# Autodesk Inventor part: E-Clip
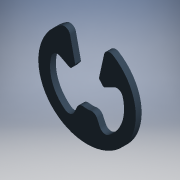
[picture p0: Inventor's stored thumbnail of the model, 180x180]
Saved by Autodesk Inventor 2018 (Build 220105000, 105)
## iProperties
Shininess: 50.0
Compacted: True
Length Units: 11272
Angle Units: 11279
Time Units: 11290
Mass Units: 11286
Length Display Precision: 4
Angle Display Precision: 2
Company: Autodesk
Created: 2000-03
Part Number: E-Clip
Project: Inventor Samples
Document SubType Name: Modeling
Designer: Autodesk, Inc.
Density: 1.13 g/cm^3
Mass: 0.00688314 g
Surface Area: 0.451156 cm^2
Volume: 0.00609128 cm^3
Material: Nylon-6/6
Appearance: Dark Blue Grey
Density: 0.0
Volumn: 0.0
Area: 0.0
PropertySet Name: Model Information
Control State: 0
Master: False
Checked Out: False
Author: Autodesk, Inc.
Revision Number: A
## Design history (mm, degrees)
node "Extrusion1" dims "d2" = 0.381, "d3" = 0
  sketch "Sketch2"
    geometry: C1 r 3.175 at (-5.202, -4.223); C2 r 1.191 at (-5.202, -4.223)
    constraints: 2 centre point, 1 coincident
    dimensions: "d0" = 2.38125 diameter of C2; "d1" = 6.35 diameter of C1
node "Extrusion2" dims "d9" = 0.381, "d10" = 0
  sketch "Sketch3"
    geometry: L1 (-0.635, 0.311)-(0.635, 0.311); L2 (0.635, 0.311)-(1.27, 3.175); L3 (1.27, 3.175)-(-1.27, 3.175); L4 (-1.27, 3.175)-(-0.635, 0.311); C1 r 1.191 at (0, 0) reference; C2 r 3.175 at (0, 0) reference
    constraints: 8 end point, 1 horizontal, 1 parallel, 1 tangent
    dimensions: "d4" = 2.54 distance of L2.end L3.end; "d5" = 1.27 distance of L1.start L1.end; "d6" = 1.27 horizontal distance of C1.centre L3.end (= 0.5 x d4); "d7" = 25 deg angle of L2 L4; "d8" = 0.635 horizontal distance of C1.centre L1.start (= 0.5 x d5)
node "Extrusion3" dims "d16" = 0.381, "d17" = 0
  sketch "Sketch4"
    geometry: L1 (-3.986, -1.29)-(-4.434, -3.313) reference; L2 (-5.97, -3.313)-(-6.418, -1.29) reference; L3 (-5.705, -5.302)-(-6.222, -6.41); L4 (-4.699, -5.302)-(-4.182, -6.41); L5 (-6.281, -4.726)-(-6.281, -4.726); L6 (-5.705, -5.302)-(-5.705, -5.302); L7 (-6.258, -3.673)-(-7.342, -3.109); L8 (-4.146, -3.673)-(-3.062, -3.109); A1 r 3.175 centre (-5.202, -4.223) between (-6.418, -1.29) and (-3.986, -1.29) reference; A2 r 2.413 centre (-5.202, -4.223) between (-7.342, -3.109) and (-3.062, -3.109); 2 further points
    constraints: 12 end point, 5 point on circle, 4 point on line, 1 centre point, 1 coincident, 1 parallel, 1 vertical alignment, 10 other
    dimensions: "d11" = 50 deg angle of L4 L3; "d12" = 0.762 radial gap between concentric circles of A1 A2; "d13" = 25 deg dimension on point (-5.202, -4.223) point (-5.202, -7.398) L3.end (= 0.5 x d11); "d14" = 50 deg angle of L2 L7; "d15" = 50 deg angle of L8 L1 (= d14)
node "Fillet1" dims "d18" = 0.381, "d19" = 0.127
workaxis "Work Axis1"
body "Solid1"
